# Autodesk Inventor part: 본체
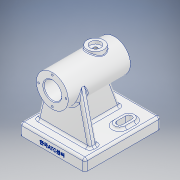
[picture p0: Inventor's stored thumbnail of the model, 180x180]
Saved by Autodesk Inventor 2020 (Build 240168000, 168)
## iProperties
Created: 2021-11
Part Number: 본체
Material: 알루미늄 6061
Document SubType Name: Modeling
Designer: user
Density: 2.7 g/cm^3
Appearance: 알루미늄 - 평지
Mass: 633.803 g
Surface Area: 513.531 cm^2
Volume: 234.742 cm^3
Author: user
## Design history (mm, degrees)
sketch "스케치1"
  geometry: C1 r 21 at (0, 0); 1 further point
  constraints: 1 centre point, 1 coincident
  dimensions: "d0" = 42 diameter of C1
extrude "돌출1" new body sketch "스케치1" stored distance "d1" = 82; taper "d2" = 0 deg
node "작업 평면1"
sketch "스케치6"
  geometry: L1 (-43, -59)-(43, -59); L2 (43, -59)-(43, 41); L3 (43, 41)-(-43, 41); L4 (-43, 41)-(-43, -59); L5 (-43, -59)-(43, 41); L6 (43, -59)-(-43, 41); L7 (21, 41)-(-21, 41) reference; 2 further points
  constraints: 12 end point, 2 midpoint, 2 parallel, 1 horizontal, 1 perpendicular
  dimensions: "d17" = 86 distance of L3.end L2.end; "d18" = 100 distance of L2.end L1.end; "d19" = 0 distance between parallel lines of L7 L3; "d20" = 43 distance from line of L4 point (0, 0)
extrude "돌출4" join sketch "스케치6" distance "d21" = 15; taper "d22" = 0 deg
node "작업 평면3"
sketch "스케치7"
  geometry: L1 (43, -57)-(43, -72) reference; L2 (43, -72)-(-43, -72) reference; L3 (-43, -72)-(-43, -57) reference; L4 (-43, -57)-(43, -57) reference; L5 (20.441, 4.814)-(35, -57); L6 (43, -57)-(-43, -57) reference; L7 (-20.441, 4.814)-(-35, -57); L8 (-35, -57)-(35, -57); L9 (43, -72)-(43, -57) reference; C1 r 21 at (0, 0) reference; A1 r 21 centre (0, 0) between (20.441, 4.814) and (-20.441, 4.814) reference; A2 r 21 centre (0, 0) between (-20.441, 4.814) and (20.441, 4.814); 5 further points
  constraints: 6 end point, 4 point on circle, 2 point on line, 2 tangent, 1 centre point, 1 coincident, 1 collinear
  dimensions: "d89" = 8 distance from line of L3 L7.end; "d90" = 8 distance from line of L9 L5.end
extrude "돌출5" join sketch "스케치7" distance "d26" = 10; taper "d27" = 0 deg
sketch "스케치8"
  geometry: L1 (21, -41)-(-21, -41) reference; L2 (-21, -41)-(-21, 16) reference; L3 (-21, 16)-(-57, 16) reference; L4 (-57, 16)-(-57, -59) reference; L5 (-57, -59)-(-72, -59) reference; L6 (-72, -59)-(-72, 41) reference; L7 (-72, 41)-(-57, 41) reference; L8 (-57, 41)-(-57, 26) reference; L9 (-57, 26)-(-21, 26) reference; L10 (-21, 26)-(-21, 41) reference; L11 (-21, 41)-(21, 41) reference; L12 (21, 41)-(21, -41) reference; L13 (-21, -41)-(-21, 41) reference; L14 (-21, -30.897)-(-57, -44); L15 (-57, 41)-(-57, -59) reference; 1 further point
  constraints: 2 end point, 2 point on line
  dimensions: "d28" = 15 distance from line of L5 L14.end; "d29" = 70 deg angle of L4 L14
feature "리브1" sketch "스케치8" dims "d30" = 1, "d31" = 10, "d32" = 0, "d33" = 0, "d34" = 1, "d35" = 1
sketch "스케치9"
  geometry: C1 r 11.5 at (0, 0); 1 further point
  constraints: 1 centre point, 1 coincident
  dimensions: "d36" = 23 diameter of C1
extrude "돌출6" cut sketch "스케치9" distance "d37" = 20; taper "d38" = 0 deg
sketch "스케치10"
  geometry: C1 r 14.5 at (0, 0); 1 further point
  constraints: 1 centre point, 1 coincident
  dimensions: "d39" = 29 diameter of C1
extrude "돌출7" cut sketch "스케치10" distance "d40" = 62; taper "d41" = 0 deg
fillet "모깎기1" dims "d42" = 3
sketch "스케치11"
  geometry: L1 (27, 33)-(27, 21); L2 (20, 33)-(20, 21); L3 (34, 21)-(34, 33); L4 (40, 59)-(-40, 59) reference; L5 (43, -38)-(43, 56) reference; A1 r 7 centre (27, 33) between (34, 33) and (20, 33); A2 r 7 centre (27, 21) between (20, 21) and (34, 21); 2 further points
  constraints: 8 end point, 4 point on circle, 4 tangent, 2 centre point, 1 midpoint, 1 parallel, 1 vertical
  dimensions: "d43" = 12 distance of L1.start L1.end; "d44" = 14 diameter of A2; "d45" = 26 distance from line of L4 L1.start; "d46" = 16 distance from line of L5 L1.start
extrude "돌출8" join sketch "스케치11" distance "d47" = 3; taper "d48" = 0 deg
sketch "스케치12"
  geometry: L1 (0, 0)-(0, 12); L2 (4, 0)-(4, 12); L3 (-4, 12)-(-4, 0); A1 r 7 centre (0, 0) between (-7, 0) and (7, 0) reference; A2 r 7 centre (0, 12) between (7, 12) and (-7, 12) reference; A3 r 4 centre (0, 0) between (-4, 0) and (4, 0); A4 r 4 centre (0, 12) between (4, 12) and (-4, 12); 2 further points
  constraints: 8 end point, 4 point on circle, 4 tangent, 2 centre point, 1 midpoint, 1 parallel, 1 vertical
  dimensions: "d49" = 8 diameter of A4
extrude "돌출9" cut sketch "스케치12" extent not by distance; stored distance "d50" = 0; taper "d51" = 0 deg
node "작업 평면4"
sketch "스케치13"
  geometry: L1 (-21, -41)-(21, -41) reference; C1 r 11 at (0, -16); 1 further point
  constraints: 1 centre point, 1 vertical alignment
  dimensions: "d53" = 22 diameter of C1; "d54" = 25 distance from line of L1 C1.centre
extrude "돌출10" join sketch "스케치13" stored distance "d55" = 3; taper "d56" = 0 deg
sketch "스케치14"
  geometry: L1 (21, 25)-(-21, 25) reference; 2 further points
  constraints: 1 vertical alignment
  dimensions: "d57" = 25 distance from line of L1 point (0, 0)
hole "구멍1" sketch "스케치14" at (0, 0) diameter "d58" = 4.917; stored, may be unused: countersink angle "d62" = 90 deg, drill point angle "d64" = 0 deg; dims "d59" = 17, "d60" = 14, "d61" = 4, "d63" = 17.1
sketch "스케치16" dims "d65" = 36
  geometry: 3 further points
  constraints: 2 vertical alignment, 1 coincident, 2 other
hole "구멍2" sketch "스케치16" at (0, 18) diameter "d66" = 2.459; stored, may be unused: countersink angle "d70" = 90 deg, drill point angle "d72" = 118 deg; dims "d67" = 8, "d68" = 14, "d69" = 4, "d71" = 10
fillet "모깎기2" dims "d76" = 3
fillet "모깎기3" dims "d77" = 3
fillet "모깎기4" dims "d78" = 3
fillet "모깎기5" dims "d79" = 3
fillet "모깎기6" dims "d80" = 3
fillet "모깎기7" dims "d81" = 3
fillet "모깎기8" dims "d82" = 1
chamfer "모따기1" distance "d83" = 1; stored, may be unused: second distance "d84" = 2, angle "d85" = 45 deg
sketch "스케치17"
  geometry: L1 (83, 0)-(80, 0) reference; 2 further points
  constraints: 1 vertical alignment, 1 other
  dimensions: "d86" = 6 distance from line of L1 point (40, 6)
extrude "돌출11" join sketch "스케치17" distance "d87" = 0.5; taper "d88" = 0 deg
node "솔리드1"
mirror "미러1"
mirror "미러2"
pattern_circular "원형 패턴1" dims angle "d74" = 360 deg
mirror "미러3"
node "절단 모서리 투영2"
node "절단 모서리 투영3"
feature "A9D066F2-1C7D-4E18-AEED-F7BC21143FA4" dims "d58" = 4.917, "d59" = 17, "d60" = 14, "d61" = 4, "d62" = 90 deg, "d63" = 17.1, "d64" = 0
other parameters: "d3" = -72, "d23" = 26, "d52" = 24
